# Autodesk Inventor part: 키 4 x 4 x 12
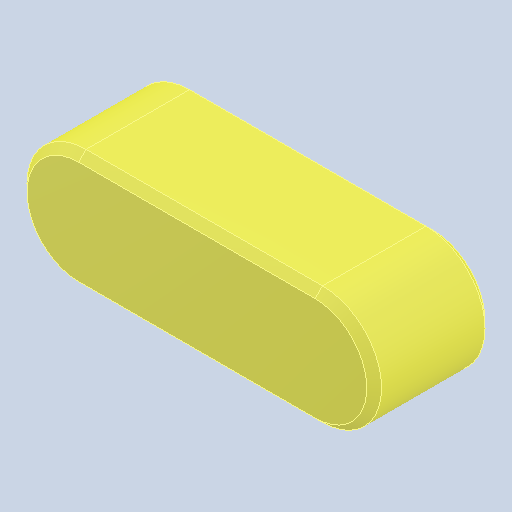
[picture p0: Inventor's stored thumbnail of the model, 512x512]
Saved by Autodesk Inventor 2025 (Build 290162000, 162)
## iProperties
Created: 2025-08
Part Number: 키 4 x 4 x 12
Material: 강철, 연강
Description: 키 및 해당 키홈
Document SubType Name: Modeling
Designer: infra02
Density: 7.85 g/cm^3
Appearance: 기본값
Author: jhkim
Sending System: Autodesk Inventor 2026
Preprocessor: ST-DEVELOPER v20.1
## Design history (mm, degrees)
feature "Solid1"
node "솔리드1"
